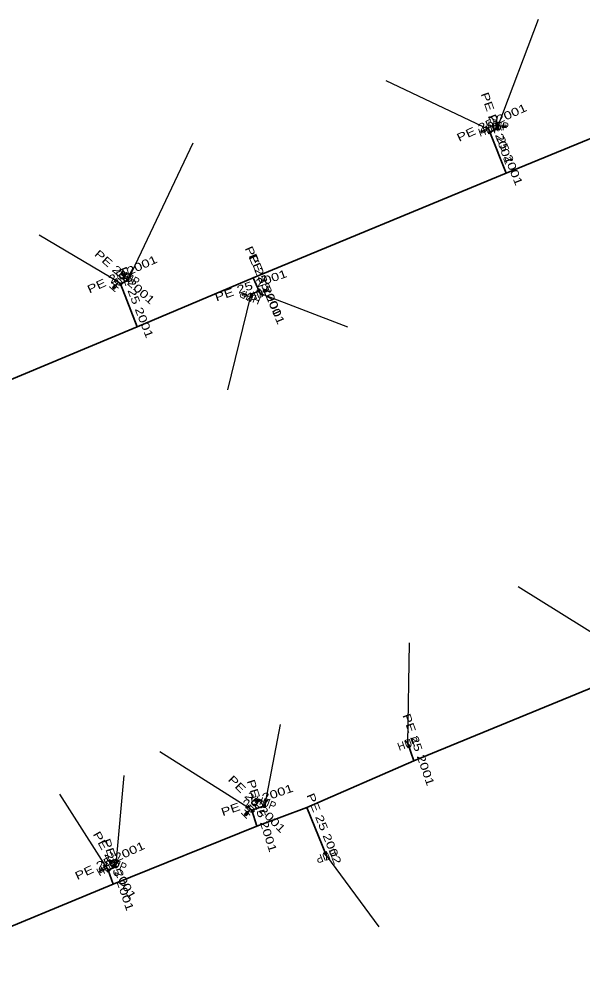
# Model space of a CAD drawing. Extents: x -737484 to -734496, y -1033882 to -1030666.
# Drawn here: x -734925.7 to -734855.3, y -1033417 to -1033296.5 of the extents above; entities that cross this region are included whole.
import ezdxf
from ezdxf.enums import TextEntityAlignment as Align

# ---------------------------------------------------------------- set-up
doc = ezdxf.new("R2010")
doc.units = 0
doc.header["$LTSCALE"] = 0.4
for name, color, linetype, lineweight in [('1', 7, 'Continuous', 13), ('22', 7, 'Continuous', 25), ('5', 7, 'Continuous', 35), ('7', 7, 'Continuous', 35)]:
    doc.layers.add(name, color=color, linetype=linetype, lineweight=lineweight)
doc.layers.add('2', color=7, linetype='Continuous')

msp = doc.modelspace()

# ---------------------------------------------------------------- linework, layer by layer
at = {"layer": '1'}
for p, q in [((-734867.628, -1033310.336), (-734867.959, -1033310.45)), ((-734867.06, -1033310.22), (-734867.532, -1033310.382)), ((-734865.89, -1033309.77), (-734865.391, -1033309.804)), ((-734865.321, -1033309.884), (-734864.972, -1033309.909)), ((-734912.468, -1033328.412), (-734912.78, -1033328.253)), ((-734911.99, -1033328.74), (-734912.435, -1033328.513)), ((-734913.763, -1033329.664), (-734913.993, -1033329.928)), ((-734913.33, -1033329.28), (-734913.658, -1033329.657)), ((-734897.395, -1033330.865), (-734897.719, -1033330.733)), ((-734895.66, -1033330.65), (-734895.199, -1033330.454)), ((-734895.101, -1033330.494), (-734894.779, -1033330.357)), ((-734896.89, -1033331.15), (-734897.353, -1033330.962)), ((-734895.459, -1033394.023), (-734895.786, -1033393.898)), ((-734894.95, -1033394.3), (-734895.416, -1033394.12)), ((-734897.26, -1033395.467), (-734897.494, -1033395.727)), ((-734896.82, -1033395.09), (-734897.154, -1033395.461)), ((-734914.099, -1033401.619), (-734914.416, -1033401.471)), ((-734913.61, -1033401.93), (-734914.063, -1033401.718)), ((-734915.315, -1033402.642), (-734915.618, -1033402.817)), ((-734914.78, -1033402.42), (-734915.213, -1033402.67))]:
    msp.add_line(p, q, dxfattribs=at)
for points in [[(-734866.053, -1033309.257), (-734865.654, -1033309.285), (-734866.123, -1033310.254), (-734865.724, -1033310.282)], [(-734868.005, -1033310.545), (-734868.054, -1033310.403), (-734867.581, -1033310.24), (-734867.532, -1033310.382)], [(-734867.981, -1033310.498), (-734868.006, -1033310.427), (-734867.604, -1033310.288), (-734867.579, -1033310.359)], [(-734868.005, -1033310.545), (-734867.956, -1033310.687), (-734867.483, -1033310.524), (-734867.532, -1033310.382)], [(-734867.41, -1033309.811), (-734867.032, -1033309.681), (-734867.085, -1033310.756), (-734866.707, -1033310.626)], [(-734864.892, -1033309.839), (-734864.902, -1033309.989), (-734865.401, -1033309.954), (-734865.391, -1033309.804)], [(-734864.892, -1033309.839), (-734864.881, -1033309.69), (-734865.38, -1033309.655), (-734865.391, -1033309.804)], [(-734864.932, -1033309.874), (-734864.938, -1033309.948), (-734865.362, -1033309.919), (-734865.356, -1033309.844)], [(-734912.881, -1033328.286), (-734912.949, -1033328.419), (-734912.503, -1033328.646), (-734912.435, -1033328.513)], [(-734912.881, -1033328.286), (-734912.812, -1033328.152), (-734912.367, -1033328.379), (-734912.435, -1033328.513)], [(-734912.83, -1033328.27), (-734912.796, -1033328.203), (-734912.417, -1033328.396), (-734912.451, -1033328.463)], [(-734911.941, -1033328.203), (-734911.584, -1033328.385), (-734912.395, -1033329.094), (-734912.038, -1033329.276)], [(-734913.986, -1033330.034), (-734914.099, -1033329.936), (-734913.771, -1033329.558), (-734913.658, -1033329.657)], [(-734913.989, -1033329.981), (-734914.045, -1033329.932), (-734913.766, -1033329.611), (-734913.71, -1033329.661)], [(-734913.986, -1033330.034), (-734913.872, -1033330.133), (-734913.544, -1033329.755), (-734913.658, -1033329.657)], [(-734913.837, -1033329.102), (-734913.575, -1033328.801), (-734913.082, -1033329.758), (-734912.82, -1033329.457)], [(-734897.817, -1033330.775), (-734897.873, -1033330.914), (-734897.409, -1033331.101), (-734897.353, -1033330.962)], [(-734897.817, -1033330.775), (-734897.76, -1033330.636), (-734897.297, -1033330.823), (-734897.353, -1033330.962)], [(-734897.768, -1033330.755), (-734897.739, -1033330.685), (-734897.345, -1033330.844), (-734897.374, -1033330.914)], [(-734896.891, -1033331.687), (-734897.262, -1033331.537), (-734896.517, -1033330.76), (-734896.888, -1033330.61)], [(-734895.28, -1033331.032), (-734895.648, -1033331.188), (-734895.671, -1033330.111), (-734896.039, -1033330.267)], [(-734894.739, -1033330.259), (-734894.798, -1033330.121), (-734895.258, -1033330.316), (-734895.199, -1033330.454)], [(-734894.739, -1033330.259), (-734894.68, -1033330.397), (-734895.141, -1033330.592), (-734895.199, -1033330.454)], [(-734894.76, -1033330.308), (-734894.73, -1033330.377), (-734895.121, -1033330.543), (-734895.151, -1033330.474)], [(-734877.51, -1033386.501), (-734877.132, -1033386.371), (-734877.185, -1033387.446), (-734876.807, -1033387.316)], [(-734897.314, -1033394.877), (-734897.032, -1033394.595), (-734896.607, -1033395.584), (-734896.325, -1033395.302)], [(-734895.883, -1033393.941), (-734895.937, -1033394.081), (-734895.47, -1033394.26), (-734895.416, -1033394.12)], [(-734895.883, -1033393.941), (-734895.829, -1033393.801), (-734895.363, -1033393.98), (-734895.416, -1033394.12)], [(-734895.834, -1033393.92), (-734895.807, -1033393.85), (-734895.411, -1033394.002), (-734895.438, -1033394.073)], [(-734894.956, -1033393.76), (-734894.583, -1033393.903), (-734895.314, -1033394.694), (-734894.941, -1033394.837)], [(-734897.489, -1033395.833), (-734897.6, -1033395.732), (-734897.266, -1033395.361), (-734897.154, -1033395.461)], [(-734897.491, -1033395.78), (-734897.546, -1033395.729), (-734897.262, -1033395.414), (-734897.206, -1033395.464)], [(-734897.489, -1033395.833), (-734897.377, -1033395.933), (-734897.043, -1033395.561), (-734897.154, -1033395.461)], [(-734886.986, -1033401.327), (-734887.357, -1033401.477), (-734887.36, -1033400.4), (-734887.731, -1033400.55)], [(-734915.196, -1033402.078), (-734914.846, -1033401.884), (-734914.711, -1033402.953), (-734914.361, -1033402.759)], [(-734914.516, -1033401.507), (-734914.579, -1033401.643), (-734914.126, -1033401.854), (-734914.063, -1033401.718)], [(-734914.516, -1033401.507), (-734914.452, -1033401.371), (-734913.999, -1033401.582), (-734914.063, -1033401.718)], [(-734914.466, -1033401.489), (-734914.434, -1033401.421), (-734914.049, -1033401.601), (-734914.081, -1033401.669)], [(-734913.607, -1033401.391), (-734913.236, -1033401.541), (-734913.981, -1033402.318), (-734913.61, -1033402.468)], [(-734915.646, -1033402.92), (-734915.721, -1033402.79), (-734915.288, -1033402.54), (-734915.213, -1033402.67)], [(-734915.631, -1033402.868), (-734915.669, -1033402.804), (-734915.301, -1033402.591), (-734915.263, -1033402.656)], [(-734915.646, -1033402.92), (-734915.571, -1033403.049), (-734915.138, -1033402.799), (-734915.213, -1033402.67)]]:
    msp.add_lwpolyline(points, close=True, dxfattribs=at)
at = {"layer": '22'}
for p, q in [((-734865.889, -1033309.77), (-734860.835, -1033296.452)), ((-734867.059, -1033310.219), (-734879.889, -1033304.129)), ((-734911.99, -1033328.74), (-734904.004, -1033311.894)), ((-734913.329, -1033329.28), (-734923.225, -1033323.402)), ((-734895.66, -1033330.65), (-734884.716, -1033334.867)), ((-734896.89, -1033331.149), (-734899.712, -1033342.73)), ((-734849.85, -1033375.78), (-734863.382, -1033367.329)), ((-734877.159, -1033386.909), (-734876.963, -1033374.332)), ((-734894.949, -1033394.299), (-734893.091, -1033384.518)), ((-734896.82, -1033395.09), (-734908.158, -1033387.914)), ((-734913.609, -1033401.93), (-734912.614, -1033390.885)), ((-734914.779, -1033402.419), (-734920.678, -1033393.219)), ((-734887.359, -1033400.939), (-734880.783, -1033409.771))]:
    msp.add_line(p, q, dxfattribs=at)
at = {"layer": '5'}
for points in [[(-735053.88, -1033393.79), (-735022.84, -1033381), (-735005.93, -1033374.05), (-735000, -1033371.64), (-734997.93, -1033370.8), (-734976.39, -1033362.7), (-734959.2, -1033355.38), (-734948.31, -1033350.41), (-734910.99, -1033334.84), (-734896.49, -1033328.75), (-734864.89, -1033315.68), (-734844.17, -1033307.16), (-734831.48, -1033302.12), (-734827.29, -1033302.17), (-734824.78, -1033302.66), (-734821.95, -1033304.62), (-734815.17, -1033312.18), (-734809.03, -1033319.75), (-734803.21, -1033327.69), (-734802.82, -1033328.28)], [(-735042.22, -1033456.86), (-735027.92, -1033450.86), (-735021.89, -1033448.42), (-735004.89, -1033441.65), (-735000, -1033439.618), (-734988.79, -1033434.96), (-734973.06, -1033428.66), (-734957.88, -1033422.63), (-734935.56, -1033413.41), (-734932.32, -1033412.04), (-734914.01, -1033404.47), (-734896.05, -1033397.2), (-734889.79, -1033394.87), (-734876.41, -1033389.06), (-734849.15, -1033377.86), (-734829.82, -1033369.94), (-734809.23, -1033361.56), (-734800.47, -1033357.83), (-734800.3, -1033357.79)]]:
    msp.add_lwpolyline(points, dxfattribs=at)
at = {"layer": '7'}
for p, q in [((-734866.94, -1033310.56), (-734867.059, -1033310.219)), ((-734864.89, -1033315.68), (-734866.94, -1033310.56)), ((-734913.09, -1033329.49), (-734913.329, -1033329.28)), ((-734910.99, -1033334.84), (-734913.09, -1033329.49)), ((-734896.49, -1033328.75), (-734895.77, -1033330.39)), ((-734895.77, -1033330.39), (-734895.66, -1033330.65)), ((-734876.41, -1033389.06), (-734877.159, -1033386.909)), ((-734896.67, -1033395.24), (-734896.82, -1033395.09)), ((-734896.05, -1033397.2), (-734896.67, -1033395.24)), ((-734889.79, -1033394.87), (-734887.359, -1033400.939)), ((-734914.61, -1033402.72), (-734914.779, -1033402.419)), ((-734914.01, -1033404.47), (-734914.61, -1033402.72))]:
    msp.add_line(p, q, dxfattribs=at)
for points in [[(-734866.94, -1033310.56), (-734865.91, -1033310.09), (-734865.889, -1033309.77)], [(-734913.09, -1033329.49), (-734912.15, -1033329.06), (-734911.99, -1033328.74)], [(-734895.77, -1033330.39), (-734896.72, -1033330.72), (-734896.89, -1033331.149)], [(-734896.67, -1033395.24), (-734895.1, -1033394.69), (-734894.949, -1033394.299)], [(-734914.61, -1033402.72), (-734913.77, -1033402.33), (-734913.609, -1033401.93)]]:
    msp.add_lwpolyline(points, dxfattribs=at)

# ---------------------------------------------------------------- texts
at = {"layer": '2', "width": 0.95}
for rotation, p in [(356, (-734865.9234, -1033310.2686)), (19, (-734866.8953, -1033310.691)), (49, (-734912.9514, -1033329.6075)), (333, (-734912.2165, -1033329.1855)), (203, (-734895.8551, -1033330.1893)), (158, (-734896.7022, -1033330.685)), (19, (-734876.9953, -1033387.381)), (339, (-734895.1277, -1033394.7653)), (45, (-734896.4661, -1033395.4431)), (202, (-734887.5462, -1033400.475)), (29, (-734914.5359, -1033402.8559)), (338, (-734913.7958, -1033402.393))]:
    msp.add_text('HUP', height=1, rotation=rotation, dxfattribs=at).set_placement(p, align=Align.CENTER)
at = {"layer": '7', "width": 1.35}
for s, rotation, p in [('PE 25 2001', 289.238, (-734866.5271, -1033310.2238)), ('PE 25 2001', 24.528, (-734866.4866, -1033309.8032)), ('PE 25 2001', 291.821, (-734865.45, -1033312.9331)), ('PE 25 2001', 293.703, (-734895.6721, -1033329.3685)), ('PE 25 2001', 24.582, (-734912.665, -1033328.745)), ('PE 25 2001', 318.695, (-734912.879, -1033329.0091)), ('PE 25 2001', 292.932, (-734895.2545, -1033330.3242)), ('PE 25 2001', 291.431, (-734911.5737, -1033331.9823)), ('PE 25 2001', 19.156, (-734896.6266, -1033330.1573)), ('PE 25 2001', 289.199, (-734876.312, -1033387.8201)), ('PE 25 2001', 315, (-734896.3911, -1033394.8109)), ('PE 25 2001', 19.306, (-734895.8518, -1033394.4237)), ('PE 25 2001', 287.554, (-734895.8826, -1033396.0687)), ('PE 25 2002', 291.829, (-734888.1095, -1033397.7181)), ('PE 25 2001', 299.313, (-734914.2579, -1033402.3247)), ('PE 25 2001', 24.905, (-734914.2046, -1033401.98)), ('PE 25 2001', 288.925, (-734913.8364, -1033403.4323))]:
    msp.add_text(s, height=1, rotation=rotation, dxfattribs=at).set_placement(p, align=Align.CENTER)

doc.saveas('drawing.dxf')
